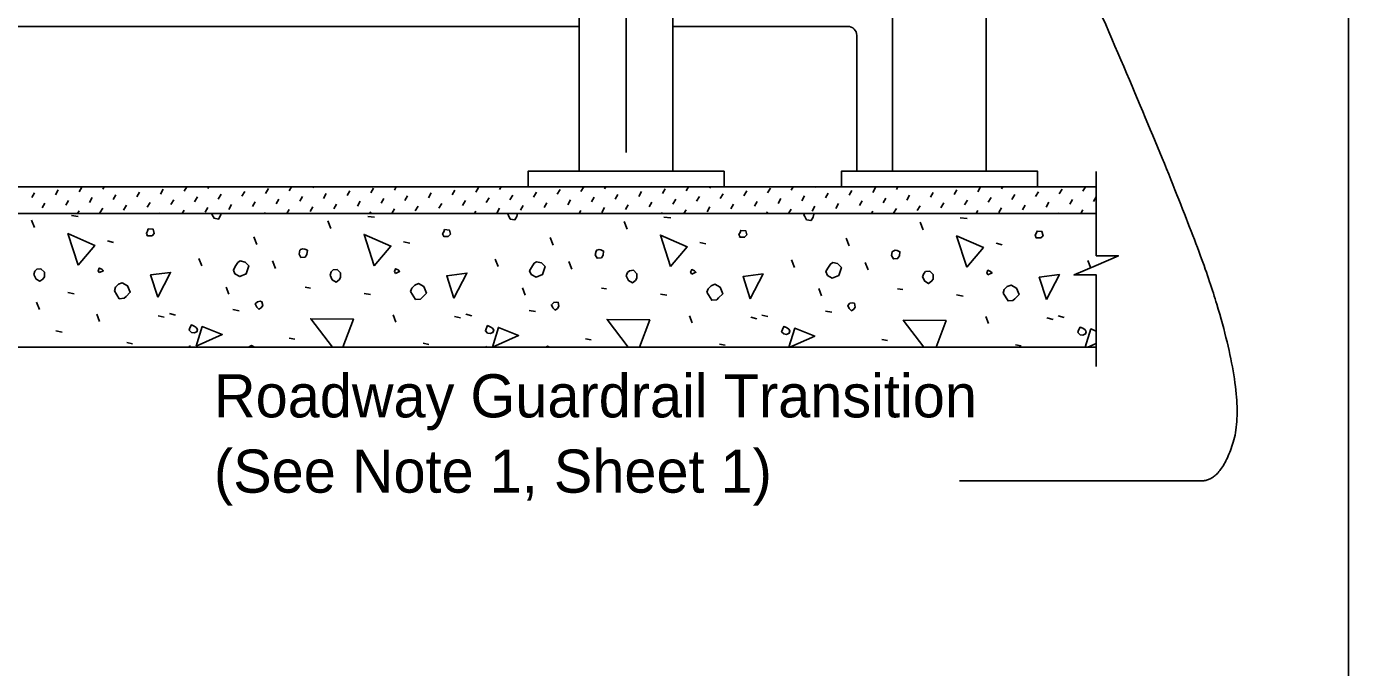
# Model space of a CAD drawing. Extents: x 21587 to 21659.1, y 56113.9 to 56155.9.
# Drawn here: x 21599.32 to 21605.5, y 56131.8 to 56134.8 of the extents above; entities that cross this region are included whole.
import ezdxf

# ---------------------------------------------------------------- set-up
doc = ezdxf.new("R2010")
doc.units = 0
for name, color, linetype in [('AdhocPoint_dp', 7, 'Continuous'), ('Patterning', 7, 'Continuous'), ('PlotBorder_dp', 7, 'Continuous'), ('TextMisc', 7, 'Continuous')]:
    doc.layers.add(name, color=color, linetype=linetype)

msp = doc.modelspace()

# ---------------------------------------------------------------- linework, layer by layer
at = {"layer": 'AdhocPoint_dp'}
for p, q in [((21593.9596, 56134.8009), (21601.9067, 56134.8009)), ((21602.3442, 56134.8009), (21603.1616, 56134.8009)), ((21603.2033, 56134.7592), (21603.2033, 56134.124)), ((21604.323, 56134.0511), (21593.9596, 56134.0511)), ((21593.9596, 56133.926), (21604.323, 56133.926)), ((21604.323, 56133.301), (21599.1795, 56133.301))]:
    msp.add_line(p, q, dxfattribs=at)
msp.add_arc((21603.1616, 56134.7592), 0.0417, 0, 90, dxfattribs=at)
at = {"layer": 'Patterning'}
for p, q in [((21602.3442, 56136.8633), (21602.3442, 56134.124)), ((21603.8089, 56136.8633), (21603.8089, 56134.124)), ((21601.9067, 56135.0302), (21601.9067, 56134.124)), ((21603.3714, 56135.0302), (21603.3714, 56134.124))]:
    msp.add_line(p, q, dxfattribs=at)
for points in [[(21602.5838, 56134.0511), (21602.5838, 56134.124), (21601.6671, 56134.124), (21601.6671, 56134.0511)], [(21604.0485, 56134.0511), (21604.0485, 56134.124), (21603.1318, 56134.124), (21603.1318, 56134.0511)]]:
    msp.add_lwpolyline(points, close=True, dxfattribs=at)
at = {"layer": 'PlotBorder_dp'}
msp.add_line((21605.5022, 56153.2872), (21605.5022, 56127.3172), dxfattribs=at)
msp.add_lwpolyline([(21604.323, 56133.2118), (21604.323, 56133.6391), (21604.2196, 56133.6391), (21604.323, 56133.6841), (21604.4263, 56133.7291), (21604.323, 56133.7291), (21604.323, 56134.1231)], dxfattribs=at)
msp.add_open_spline([(21603.6831, 56132.6764), (21604.7157, 56132.6764), (21604.9111, 56132.6764), (21605.0214, 56133.0621), (21604.7358, 56133.994), (21603.9968, 56135.6523)], degree=2, dxfattribs=at)
at = {"layer": 'TextMisc'}
for p, q in [((21602.1255, 56134.2122), (21602.1255, 56137.1851)), ((21599.4578, 56134.0141), (21599.4708, 56134.0365)), ((21599.5684, 56134.0271), (21599.5814, 56134.0495)), ((21599.6791, 56134.04), (21599.6855, 56134.0511)), ((21599.9492, 56134.0171), (21599.9621, 56134.0395)), ((21600.0598, 56134.0301), (21600.072, 56134.0511)), ((21600.1704, 56134.0431), (21600.1751, 56134.0511)), ((21600.4405, 56134.0202), (21600.4535, 56134.0426)), ((21600.5512, 56134.0331), (21600.5616, 56134.0511)), ((21600.6618, 56134.0461), (21600.6647, 56134.0511)), ((21600.9319, 56134.0232), (21600.9449, 56134.0456)), ((21601.0425, 56134.0361), (21601.0512, 56134.0511)), ((21601.1532, 56134.0491), (21601.1543, 56134.0511)), ((21601.3126, 56134.0132), (21601.3256, 56134.0356)), ((21601.4233, 56134.0262), (21601.4362, 56134.0486)), ((21601.5339, 56134.0392), (21601.5408, 56134.0511)), ((21601.804, 56134.0163), (21601.817, 56134.0386)), ((21601.9146, 56134.0292), (21601.9273, 56134.0511)), ((21602.0253, 56134.0422), (21602.0304, 56134.0511)), ((21602.2954, 56134.0193), (21602.3083, 56134.0417)), ((21602.406, 56134.0322), (21602.4169, 56134.0511)), ((21602.5166, 56134.0452), (21602.52, 56134.0511)), ((21602.7867, 56134.0223), (21602.7997, 56134.0447)), ((21602.8974, 56134.0353), (21602.9065, 56134.0511)), ((21603.008, 56134.0482), (21603.0097, 56134.0511)), ((21603.2781, 56134.0253), (21603.2911, 56134.0477)), ((21603.3887, 56134.0383), (21603.3961, 56134.0511)), ((21603.6588, 56134.0154), (21603.6718, 56134.0378)), ((21603.7695, 56134.0283), (21603.7824, 56134.0507)), ((21603.8801, 56134.0413), (21603.8858, 56134.0511)), ((21604.1502, 56134.0184), (21604.1632, 56134.0408)), ((21604.2608, 56134.0314), (21604.2723, 56134.0511)), ((21599.3472, 56134.0012), (21599.3601, 56134.0235)), ((21599.396, 56133.9523), (21599.409, 56133.9747)), ((21599.5066, 56133.9653), (21599.5196, 56133.9877)), ((21599.6173, 56133.9782), (21599.6302, 56134.0006)), ((21599.7279, 56133.9912), (21599.7409, 56134.0136)), ((21599.8385, 56134.0042), (21599.8515, 56134.0266)), ((21599.8874, 56133.9553), (21599.9003, 56133.9777)), ((21599.998, 56133.9683), (21600.011, 56133.9907)), ((21600.1086, 56133.9813), (21600.1216, 56134.0037)), ((21600.2193, 56133.9942), (21600.2322, 56134.0166)), ((21600.3299, 56134.0072), (21600.3429, 56134.0296)), ((21600.3787, 56133.9584), (21600.3917, 56133.9808)), ((21600.4894, 56133.9713), (21600.5023, 56133.9937)), ((21600.6, 56133.9843), (21600.613, 56134.0067)), ((21600.7106, 56133.9973), (21600.7236, 56134.0196)), ((21600.8213, 56134.0102), (21600.8342, 56134.0326)), ((21600.8701, 56133.9614), (21600.8831, 56133.9838)), ((21600.9807, 56133.9743), (21600.9937, 56133.9967)), ((21601.0914, 56133.9873), (21601.1043, 56134.0097)), ((21601.202, 56134.0003), (21601.215, 56134.0227)), ((21601.2508, 56133.9514), (21601.2638, 56133.9738)), ((21601.3615, 56133.9644), (21601.3744, 56133.9868)), ((21601.4721, 56133.9774), (21601.4851, 56133.9998)), ((21601.5827, 56133.9903), (21601.5957, 56134.0127)), ((21601.6934, 56134.0033), (21601.7063, 56134.0257)), ((21601.7422, 56133.9545), (21601.7552, 56133.9768)), ((21601.8528, 56133.9674), (21601.8658, 56133.9898)), ((21601.9635, 56133.9804), (21601.9764, 56134.0028)), ((21602.0741, 56133.9933), (21602.0871, 56134.0157)), ((21602.1847, 56134.0063), (21602.1977, 56134.0287)), ((21602.2336, 56133.9575), (21602.2465, 56133.9799)), ((21602.3442, 56133.9704), (21602.3572, 56133.9928)), ((21602.4548, 56133.9834), (21602.4678, 56134.0058)), ((21602.5655, 56133.9964), (21602.5784, 56134.0188)), ((21602.6761, 56134.0093), (21602.6891, 56134.0317)), ((21602.7249, 56133.9605), (21602.7379, 56133.9829)), ((21602.8356, 56133.9735), (21602.8485, 56133.9959)), ((21602.9462, 56133.9864), (21602.9592, 56134.0088)), ((21603.0568, 56133.9994), (21603.0698, 56134.0218)), ((21603.1675, 56134.0124), (21603.1804, 56134.0347)), ((21603.2163, 56133.9635), (21603.2293, 56133.9859)), ((21603.3269, 56133.9765), (21603.3399, 56133.9989)), ((21603.4376, 56133.9894), (21603.4505, 56134.0118)), ((21603.5482, 56134.0024), (21603.5612, 56134.0248)), ((21603.597, 56133.9536), (21603.61, 56133.976)), ((21603.7077, 56133.9665), (21603.7206, 56133.9889)), ((21603.8183, 56133.9795), (21603.8313, 56134.0019)), ((21603.9289, 56133.9925), (21603.9419, 56134.0149)), ((21604.0396, 56134.0054), (21604.0525, 56134.0278)), ((21604.0884, 56133.9566), (21604.1014, 56133.979)), ((21604.199, 56133.9696), (21604.212, 56133.9919)), ((21604.3097, 56133.9825), (21604.3226, 56134.0049)), ((21599.5332, 56133.9165), (21599.565, 56133.913)), ((21599.561, 56133.926), (21599.5684, 56133.9388)), ((21599.6661, 56133.9294), (21599.6791, 56133.9518)), ((21599.7767, 56133.9424), (21599.7897, 56133.9648)), ((21599.9475, 56133.926), (21599.9492, 56133.9289)), ((21600.0506, 56133.926), (21600.0598, 56133.9419)), ((21600.1575, 56133.9324), (21600.1704, 56133.9548)), ((21600.2681, 56133.9454), (21600.2811, 56133.9678)), ((21600.4371, 56133.926), (21600.4405, 56133.9319)), ((21600.5403, 56133.926), (21600.5512, 56133.9449)), ((21600.6488, 56133.9355), (21600.6618, 56133.9578)), ((21600.7595, 56133.9484), (21600.7724, 56133.9708)), ((21600.9179, 56133.913), (21600.9497, 56133.9094)), ((21600.9267, 56133.926), (21600.9319, 56133.9349)), ((21601.0299, 56133.926), (21601.0425, 56133.9479)), ((21601.1402, 56133.9385), (21601.1532, 56133.9609)), ((21601.4164, 56133.926), (21601.4233, 56133.938)), ((21601.5209, 56133.9285), (21601.5339, 56133.9509)), ((21601.6316, 56133.9415), (21601.6445, 56133.9639)), ((21601.8028, 56133.926), (21601.804, 56133.928)), ((21601.906, 56133.926), (21601.9146, 56133.941)), ((21602.0123, 56133.9315), (21602.0253, 56133.9539)), ((21602.1229, 56133.9445), (21602.1359, 56133.9669)), ((21602.2925, 56133.926), (21602.2954, 56133.931)), ((21602.3956, 56133.926), (21602.406, 56133.944)), ((21602.5037, 56133.9346), (21602.5166, 56133.957)), ((21602.6143, 56133.9475), (21602.6273, 56133.9699)), ((21602.7821, 56133.926), (21602.7867, 56133.9341)), ((21602.8852, 56133.926), (21602.8974, 56133.947)), ((21602.995, 56133.9376), (21603.008, 56133.96)), ((21603.1057, 56133.9506), (21603.1186, 56133.9729)), ((21603.2717, 56133.926), (21603.2781, 56133.9371)), ((21603.3758, 56133.9276), (21603.3887, 56133.95)), ((21603.4864, 56133.9406), (21603.4994, 56133.963)), ((21603.6582, 56133.926), (21603.6588, 56133.9271)), ((21603.7613, 56133.926), (21603.7695, 56133.9401)), ((21603.8671, 56133.9307), (21603.8801, 56133.9531)), ((21603.9778, 56133.9436), (21603.9907, 56133.966)), ((21604.1478, 56133.926), (21604.1502, 56133.9302)), ((21604.2509, 56133.926), (21604.2608, 56133.9431)), ((21599.3606, 56133.8606), (21599.3465, 56133.8959)), ((21600.7453, 56133.857), (21600.7311, 56133.8924)), ((21602.13, 56133.8535), (21602.1158, 56133.8889)), ((21602.3026, 56133.9094), (21602.3344, 56133.9059)), ((21603.5146, 56133.85), (21603.5005, 56133.8853)), ((21603.6873, 56133.9059), (21603.7191, 56133.9024)), ((21599.7012, 56133.7981), (21599.7294, 56133.791)), ((21600.3994, 56133.7822), (21600.3853, 56133.8175)), ((21601.0858, 56133.7945), (21601.1141, 56133.7875)), ((21601.7841, 56133.7786), (21601.77, 56133.814)), ((21602.4705, 56133.791), (21602.4988, 56133.7839)), ((21603.1688, 56133.7751), (21603.1546, 56133.8104)), ((21603.8552, 56133.7875), (21603.8835, 56133.7804)), ((21600.1431, 56133.6814), (21600.129, 56133.7168)), ((21600.4872, 56133.6697), (21600.473, 56133.705)), ((21601.5278, 56133.6779), (21601.5136, 56133.7132)), ((21601.8719, 56133.6661), (21601.8577, 56133.7015)), ((21602.9125, 56133.6743), (21602.8983, 56133.7097)), ((21603.2565, 56133.6626), (21603.2424, 56133.6979)), ((21604.2971, 56133.6708), (21604.283, 56133.7062)), ((21599.5162, 56133.5565), (21599.5462, 56133.5512)), ((21600.2686, 56133.5488), (21600.2562, 56133.5824)), ((21600.6251, 56133.5813), (21600.6498, 56133.5777)), ((21600.9008, 56133.553), (21600.9309, 56133.5477)), ((21601.6533, 56133.5453), (21601.6409, 56133.5789)), ((21602.0098, 56133.5777), (21602.0345, 56133.5742)), ((21602.2855, 56133.5494), (21602.3156, 56133.5441)), ((21603.038, 56133.5417), (21603.0256, 56133.5753)), ((21603.3944, 56133.5742), (21603.4192, 56133.5707)), ((21603.6702, 56133.5459), (21603.7003, 56133.5406)), ((21599.3845, 56133.4774), (21599.3704, 56133.5127)), ((21599.6647, 56133.4222), (21599.6523, 56133.4558)), ((21599.9387, 56133.4487), (21599.967, 56133.4416)), ((21599.9911, 56133.4587), (21600.0194, 56133.4516)), ((21600.2874, 56133.477), (21600.3175, 56133.4717)), ((21601.0493, 56133.4186), (21601.037, 56133.4522)), ((21601.3233, 56133.4451), (21601.3516, 56133.4381)), ((21601.3758, 56133.4551), (21601.404, 56133.4481)), ((21601.6721, 56133.4734), (21601.7022, 56133.4681)), ((21602.434, 56133.4151), (21602.4216, 56133.4487)), ((21602.708, 56133.4416), (21602.7363, 56133.4345)), ((21602.7604, 56133.4516), (21602.7887, 56133.4445)), ((21603.0568, 56133.4699), (21603.0868, 56133.4646)), ((21603.8187, 56133.4116), (21603.8063, 56133.4451)), ((21604.0927, 56133.4381), (21604.121, 56133.431)), ((21604.1451, 56133.4481), (21604.1734, 56133.441)), ((21599.4598, 56133.3773), (21599.4898, 56133.372)), ((21599.7919, 56133.3232), (21599.8185, 56133.3179)), ((21600.088, 56133.301), (21600.0848, 56133.3097)), ((21600.5508, 56133.3444), (21600.5773, 56133.3391)), ((21601.1766, 56133.3196), (21601.2031, 56133.3143)), ((21601.4713, 56133.301), (21601.4694, 56133.3061)), ((21601.9355, 56133.3408), (21601.962, 56133.3355)), ((21602.5613, 56133.3161), (21602.5878, 56133.3108)), ((21602.8547, 56133.301), (21602.8541, 56133.3026)), ((21603.3202, 56133.3373), (21603.3467, 56133.332)), ((21603.946, 56133.3126), (21603.9725, 56133.3073))]:
    msp.add_line(p, q, dxfattribs=at)
for points in [[(21600.1878, 56133.926), (21600.1908, 56133.9201)], [(21600.1908, 56133.9201), (21600.1997, 56133.9041), (21600.2209, 56133.9006), (21600.2297, 56133.9165), (21600.2321, 56133.926)], [(21601.5728, 56133.926), (21601.572, 56133.9236), (21601.5755, 56133.9165)], [(21601.5755, 56133.9165), (21601.5843, 56133.9006), (21601.6056, 56133.8971), (21601.6144, 56133.913), (21601.6177, 56133.926)], [(21602.9586, 56133.926), (21602.9566, 56133.9201), (21602.9602, 56133.913)], [(21602.9602, 56133.913), (21602.969, 56133.8971), (21602.9902, 56133.8935), (21602.9991, 56133.9094), (21603.0026, 56133.9236), (21603.0002, 56133.926)], [(21599.8885, 56133.8228), (21599.9098, 56133.8228), (21599.9204, 56133.8334), (21599.9151, 56133.8529), (21599.8921, 56133.8546), (21599.8885, 56133.844), (21599.8832, 56133.8352), (21599.8885, 56133.8228), (21599.885, 56133.8264)], [(21601.2732, 56133.8193), (21601.2944, 56133.8193), (21601.305, 56133.8299), (21601.2997, 56133.8493), (21601.2768, 56133.8511), (21601.2732, 56133.8405), (21601.2679, 56133.8317), (21601.2732, 56133.8193), (21601.2697, 56133.8228)], [(21599.5639, 56133.6856), (21599.5162, 56133.8323), (21599.6417, 56133.7775), (21599.5639, 56133.6856)], [(21600.9486, 56133.682), (21600.9008, 56133.8288), (21601.0264, 56133.774), (21600.9486, 56133.682)], [(21602.3333, 56133.6785), (21602.2855, 56133.8252), (21602.411, 56133.7704), (21602.3333, 56133.6785)], [(21602.6579, 56133.8158), (21602.6791, 56133.8158), (21602.6897, 56133.8264), (21602.6844, 56133.8458), (21602.6614, 56133.8476), (21602.6579, 56133.837), (21602.6526, 56133.8281), (21602.6579, 56133.8158), (21602.6544, 56133.8193)], [(21603.7179, 56133.675), (21603.6702, 56133.8217), (21603.7957, 56133.7669), (21603.7179, 56133.675)], [(21604.0426, 56133.8122), (21604.0638, 56133.8122), (21604.0744, 56133.8228), (21604.0691, 56133.8423), (21604.0461, 56133.844), (21604.0426, 56133.8334), (21604.0373, 56133.8246), (21604.0426, 56133.8122), (21604.039, 56133.8158)], [(21600.5968, 56133.7368), (21600.6056, 56133.7209), (21600.6251, 56133.7227), (21600.6339, 56133.7351), (21600.6357, 56133.7545), (21600.6233, 56133.7598), (21600.6145, 56133.7616), (21600.6039, 56133.758), (21600.6003, 56133.7545), (21600.5968, 56133.7368)], [(21601.9815, 56133.7333), (21601.9903, 56133.7174), (21602.0098, 56133.7192), (21602.0186, 56133.7315), (21602.0204, 56133.751), (21602.008, 56133.7563), (21601.9991, 56133.758), (21601.9885, 56133.7545), (21601.985, 56133.751), (21601.9815, 56133.7333)], [(21603.3661, 56133.7298), (21603.375, 56133.7138), (21603.3944, 56133.7156), (21603.4033, 56133.728), (21603.405, 56133.7474), (21603.3927, 56133.7527), (21603.3838, 56133.7545), (21603.3732, 56133.751), (21603.3697, 56133.7474), (21603.3661, 56133.7298)], [(21599.3571, 56133.6414), (21599.3677, 56133.6202), (21599.3854, 56133.6096), (21599.3995, 56133.6202), (21599.4066, 56133.6308), (21599.4066, 56133.652), (21599.3907, 56133.6679), (21599.3712, 56133.6661), (21599.3624, 56133.6573), (21599.3571, 56133.6414)], [(21599.6629, 56133.6502), (21599.6823, 56133.659), (21599.6753, 56133.6661), (21599.6629, 56133.6714), (21599.6576, 56133.659), (21599.6629, 56133.6502)], [(21600.2969, 56133.6443), (21600.3199, 56133.6319), (21600.3499, 56133.6443), (21600.3623, 56133.6814), (21600.3446, 56133.6991), (21600.3216, 56133.7044), (21600.311, 56133.6973), (21600.2987, 56133.6779), (21600.2898, 56133.662), (21600.2969, 56133.6443)], [(21601.0476, 56133.6467), (21601.067, 56133.6555), (21601.0599, 56133.6626), (21601.0476, 56133.6679), (21601.0423, 56133.6555), (21601.0476, 56133.6467)], [(21601.6816, 56133.6407), (21601.7046, 56133.6284), (21601.7346, 56133.6407), (21601.747, 56133.6779), (21601.7293, 56133.6955), (21601.7063, 56133.7008), (21601.6957, 56133.6938), (21601.6833, 56133.6743), (21601.6745, 56133.6584), (21601.6816, 56133.6407)], [(21603.0663, 56133.6372), (21603.0892, 56133.6248), (21603.1193, 56133.6372), (21603.1317, 56133.6743), (21603.114, 56133.692), (21603.091, 56133.6973), (21603.0804, 56133.6902), (21603.068, 56133.6708), (21603.0592, 56133.6549), (21603.0663, 56133.6372)], [(21599.9363, 56133.5347), (21599.9027, 56133.639), (21599.9964, 56133.6514), (21599.9363, 56133.5347)], [(21600.7417, 56133.6378), (21600.7524, 56133.6166), (21600.77, 56133.606), (21600.7842, 56133.6166), (21600.7912, 56133.6272), (21600.7912, 56133.6484), (21600.7753, 56133.6644), (21600.7559, 56133.6626), (21600.7471, 56133.6537), (21600.7417, 56133.6378)], [(21601.3209, 56133.5311), (21601.2874, 56133.6354), (21601.3811, 56133.6478), (21601.3209, 56133.5311)], [(21602.1264, 56133.6343), (21602.137, 56133.6131), (21602.1547, 56133.6025), (21602.1689, 56133.6131), (21602.1759, 56133.6237), (21602.1759, 56133.6449), (21602.16, 56133.6608), (21602.1406, 56133.659), (21602.1317, 56133.6502), (21602.1264, 56133.6343)], [(21602.4322, 56133.6431), (21602.4517, 56133.652), (21602.4446, 56133.659), (21602.4322, 56133.6644), (21602.4269, 56133.652), (21602.4322, 56133.6431)], [(21602.7056, 56133.5276), (21602.672, 56133.6319), (21602.7657, 56133.6443), (21602.7056, 56133.5276)], [(21603.5111, 56133.6308), (21603.5217, 56133.6096), (21603.5394, 56133.5989), (21603.5535, 56133.6096), (21603.5606, 56133.6202), (21603.5606, 56133.6414), (21603.5447, 56133.6573), (21603.5252, 56133.6555), (21603.5164, 56133.6467), (21603.5111, 56133.6308)], [(21603.8169, 56133.6396), (21603.8364, 56133.6484), (21603.8293, 56133.6555), (21603.8169, 56133.6608), (21603.8116, 56133.6484), (21603.8169, 56133.6396)], [(21604.0903, 56133.5241), (21604.0567, 56133.6284), (21604.1504, 56133.6407), (21604.0903, 56133.5241)], [(21599.7336, 56133.5654), (21599.7566, 56133.5282), (21599.7796, 56133.53), (21599.7884, 56133.5388), (21599.8079, 56133.5583), (21599.7955, 56133.5883), (21599.7707, 56133.6025), (21599.7531, 56133.5954), (21599.7389, 56133.5813), (21599.7336, 56133.5654)], [(21601.1183, 56133.5618), (21601.1413, 56133.5247), (21601.1642, 56133.5265), (21601.1731, 56133.5353), (21601.1925, 56133.5547), (21601.1802, 56133.5848), (21601.1554, 56133.5989), (21601.1377, 56133.5919), (21601.1236, 56133.5777), (21601.1183, 56133.5618)], [(21602.503, 56133.5583), (21602.5259, 56133.5212), (21602.5489, 56133.5229), (21602.5578, 56133.5318), (21602.5772, 56133.5512), (21602.5648, 56133.5813), (21602.5401, 56133.5954), (21602.5224, 56133.5883), (21602.5083, 56133.5742), (21602.503, 56133.5583)], [(21603.8876, 56133.5547), (21603.9106, 56133.5176), (21603.9336, 56133.5194), (21603.9424, 56133.5282), (21603.9619, 56133.5477), (21603.9495, 56133.5777), (21603.9248, 56133.5919), (21603.9071, 56133.5848), (21603.8929, 56133.5707), (21603.8876, 56133.5547)], [(21600.3988, 56133.4893), (21600.4094, 56133.4787), (21600.42, 56133.4858), (21600.4271, 56133.4964), (21600.4236, 56133.5141), (21600.4147, 56133.5159), (21600.4023, 56133.5141), (21600.3917, 56133.5035), (21600.3988, 56133.4893)], [(21601.7835, 56133.4858), (21601.7941, 56133.4752), (21601.8047, 56133.4823), (21601.8118, 56133.4929), (21601.8082, 56133.5106), (21601.7994, 56133.5123), (21601.787, 56133.5106), (21601.7764, 56133.4999), (21601.7835, 56133.4858)], [(21603.1682, 56133.4823), (21603.1788, 56133.4717), (21603.1894, 56133.4787), (21603.1964, 56133.4893), (21603.1929, 56133.507), (21603.1841, 56133.5088), (21603.1717, 56133.507), (21603.1611, 56133.4964), (21603.1682, 56133.4823)], [(21600.7531, 56133.301), (21600.6516, 56133.4345), (21600.8513, 56133.4328), (21600.8021, 56133.301)], [(21602.1351, 56133.301), (21602.0363, 56133.431), (21602.236, 56133.4292), (21602.1881, 56133.301)], [(21603.5171, 56133.301), (21603.4209, 56133.4275), (21603.6207, 56133.4257), (21603.5741, 56133.301)], [(21600.0936, 56133.3703), (21600.106, 56133.3685), (21600.1184, 56133.3738), (21600.1219, 56133.3844), (21600.1166, 56133.3933), (21600.106, 56133.4003), (21600.0936, 56133.4056), (21600.0865, 56133.3915), (21600.083, 56133.3809), (21600.0936, 56133.3703)], [(21600.116, 56133.3055), (21600.1442, 56133.3974), (21600.2379, 56133.3603), (21600.116, 56133.3055)], [(21601.4783, 56133.3667), (21601.4907, 56133.365), (21601.503, 56133.3703), (21601.5066, 56133.3809), (21601.5013, 56133.3897), (21601.4907, 56133.3968), (21601.4783, 56133.4021), (21601.4712, 56133.388), (21601.4677, 56133.3773), (21601.4783, 56133.3667)], [(21601.5006, 56133.302), (21601.5289, 56133.3939), (21601.6226, 56133.3568), (21601.5006, 56133.302)], [(21602.863, 56133.3632), (21602.8753, 56133.3614), (21602.8877, 56133.3667), (21602.8912, 56133.3773), (21602.8859, 56133.3862), (21602.8753, 56133.3933), (21602.863, 56133.3986), (21602.8559, 56133.3844), (21602.8524, 56133.3738), (21602.863, 56133.3632)], [(21602.8861, 56133.301), (21602.9136, 56133.3903), (21603.0073, 56133.3532), (21602.891, 56133.301)], [(21604.2476, 56133.3597), (21604.26, 56133.3579), (21604.2724, 56133.3632), (21604.2759, 56133.3738), (21604.2706, 56133.3827), (21604.26, 56133.3897), (21604.2476, 56133.395), (21604.2406, 56133.3809), (21604.237, 56133.3703), (21604.2476, 56133.3597)], [(21604.2719, 56133.301), (21604.2983, 56133.3868), (21604.323, 56133.377)], [(21600.3884, 56133.301), (21600.3882, 56133.302), (21600.3741, 56133.309), (21600.3606, 56133.301)], [(21601.7677, 56133.301), (21601.7587, 56133.3055), (21601.7512, 56133.301)], [(21603.1453, 56133.301), (21603.1434, 56133.302), (21603.1418, 56133.301)], [(21604.323, 56133.3187), (21604.2836, 56133.301)]]:
    msp.add_lwpolyline(points, dxfattribs=at)

# ---------------------------------------------------------------- texts
at = {"layer": 'PlotBorder_dp'}
for s, p in [('Roadway Guardrail Transition ', (21600.1992, 56132.9732)), ('(See Note 1, Sheet 1)', (21600.1992, 56132.6212))]:
    msp.add_text(s, height=0.2016, dxfattribs=at).set_placement(p)

doc.saveas('drawing.dxf')
